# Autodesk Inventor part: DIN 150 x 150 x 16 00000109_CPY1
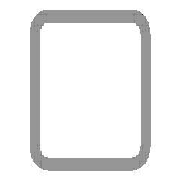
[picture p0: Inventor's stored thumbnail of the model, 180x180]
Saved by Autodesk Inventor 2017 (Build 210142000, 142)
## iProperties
Created: 2017-11
Part Number: DIN 150 x 150 x 16 00000109_CPY1
Material: Steel, Mild
Description: Cold formed welded structural hollow sections of non-alloy and fine grain structural steel
Document SubType Name: Modeling
Standard: DIN
Designer: iusti
Standard Revision: 2006-07
Standards Organization: DIN
Language: en-US
Size Designation: 150 x 150 x 16
Categories: <MemberInstance><Categories><Category DisplayName="Structural Shapes" InternalName="089c4875-fa83-4c05-b084-43b9cc11f5ed" Mnemonic="GRDR"><CategoryParameter Dis
Stock Number: 150 x 150 x 16
Mass: 49891.9 g
Surface Area: 8094.11 cm^2
Volume: 6355.65 cm^3
Density: 7.85 g/cm^3
Appearance: Semi-Polished
IsCustomPart: 1
G_W: 150.000 mm
G_H: 150.000 mm
G_L: 850.000 mm
+3725B7E9-7AF2-4E59-89A6-3A300E17AA57+CUTDETAIL3: Cut
+D51DAF0C-9B75-4607-A0B5-4213B0D9FE2B+CUTDETAIL4: Cut
_CCFamilyMember: 76
_CCFamilyDisplayName: DIN EN 10219-2 (Square Hollow Section - Cold Formed) - Cold formed welded structural hollow sections of non-alloy and fine grain structural steel
_FrameMemberDoc: Frame Member File
_Version: 15.0.0
_GetPNFromCC: 1
Author: iusti
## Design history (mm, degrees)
node "Start plane"
node "End plane"
sketch "Sketch"
  geometry: L1 (-75, -27)-(-75, 27); L2 (-27, 75)-(27, 75); L3 (75, 27)-(75, -27); L4 (27, -75)-(-27, -75); L5 (-27, 59)-(27, 59); L6 (59, 27)-(59, -27); L7 (27, -59)-(-27, -59); L8 (-59, -27)-(-59, 27); L9 (0, 118.918)-(0, -118.918) reference; L10 (-118.918, 0)-(118.918, 0) reference; A1 r 48 centre (-27, -27) between (-75, -27) and (-27, -75); A2 r 48 centre (-27, 27) between (-27, 75) and (-75, 27); A3 r 48 centre (27, 27) between (75, 27) and (27, 75); A4 r 48 centre (27, -27) between (27, -75) and (75, -27); A5 r 32 centre (-27, 27) between (-27, 59) and (-59, 27); A6 r 32 centre (27, 27) between (59, 27) and (27, 59); A7 r 32 centre (27, -27) between (27, -59) and (59, -27); A8 r 32 centre (-27, -27) between (-59, -27) and (-27, -59)
  constraints: 16 end point, 16 point on circle, 8 centre point, 8 tangent, 4 parallel, 3 equal radius, 2 perpendicular, 7 other
  dimensions: "d7" = 48 radius of A1 (= G_IR); "d10" = 150 distance between parallel lines of L2 L4 (= G_H); "d11" = 150 distance between parallel lines of L1 L3 (= G_W); "d12" = 16 distance between parallel lines of L3 L6 (= G_T); "d15" = 75 distance between parallel lines of L2 L10 (= 0.5 x d10); "d16" = 75 distance between parallel lines of L9 L3 (= 0.5 x d11)
extrude "Body" new body sketch "Sketch" stored distance "d3" = 850 (= G_L); taper "d4" = 0 deg
node "Driven Length"
  sketch "Sketch3"
    geometry: L1 (0, 0)-(10, 0) reference
    constraints: 2 end point, 1 horizontal
  workplane "Work Plane3"
  sketch "Sketch4"
    geometry: L1 (-2, 75)-(12, 75) reference; L2 (-2, 925)-(12, 925) reference
    dimensions: "d18" = 850 distance between parallel lines of L1 L2 (derived)
workplane "Work Plane4"
split "Split1"
workplane "Work Plane5"
split "Split2"
body "Solid1"
other parameters: "G_W" = 150 [user parameter; used in 1 equation term], "G_H" = 150 [user parameter; used in 1 equation term], "G_T" = 16 [user parameter; used in 1 equation term], "G_IR" = 48 [user parameter; used in 1 equation term], "G_L" = 850 (= d18) [user parameter; used in 1 equation term], "G_OFFSET_START" = -75 [user parameter; used in 1 equation term], "G_OFFSET_END" = -110.90437 [user parameter; used in 1 equation term], "d13" = 75 (= -G_OFFSET_START), "d14" = 925 (= G_OFFSET_END + B_L), "B_L" = 1035.90437 [user parameter; used in 1 equation term], "d17" = 90 deg
